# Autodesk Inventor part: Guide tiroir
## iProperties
Author: Flavien MARTY
Shininess: 100.0
PropertySet Name: _Private Model Information
Created: 2001-10
Part Number: Guide tiroir
Material: Par défaut
Document SubType Name: Modélisation
Designer: Flavien MARTY
Control State: 0
Master: False
Checked Out: False
PropertySet Name: Design Tracking Control
Density: 0.0
Volumn: 0.0
Area: 0.0
PropertySet Name: Model Information
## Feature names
1. Base1
